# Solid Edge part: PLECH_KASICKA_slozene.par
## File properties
Author: Acer
Template: Iso Metric Part.par
Last saved by: Acer
Revision: 41
Application: Solid Edge
Density: 8027,000 kg/m^3
Accuracy: 0,990
Material Thickness: 2,00 mm
Bend Radius: 1,00 mm
Relief Width: 1,00 mm
Relief Length: 0,00 mm
Neutral Factor: 0,330
Minimum Arc Length: 0,10 mm
Deviational Tolerance: 0,10 mm
Username: Acer
Typ obsahu dokumentu: 0
Material: Stainless Steel, 303
Face Style: Steel
Fill Style: ANSI32(Steel)
Virtual Style: ANSI32(Steel)
Grouping: Metals\Steel
LibraryName: Materials
Coef. of Thermal Exp: 1.7e-05
Thermal Conductivity: 17.0
Specific Heat: 502.0
Modulus of Elasticity: 193053196000.0
Poisson's Ratio: 0.29
Yield Stress: 255106009.0
Ultimate Stress: 579159588.0
Elongation: 0.0
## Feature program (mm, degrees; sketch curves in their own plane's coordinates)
sketch for "unnamed Protrusion 1" plane through (0, 0, 0) normal (0, 0, 1) x-axis (1, 0, 0)
  line (-50, -30) -> (50, -30)
  line (50, -30) -> (50, 30)
  line (50, 30) -> (-50, 30)
  line (-50, 30) -> (-50, -30)
  dimension (linear) = 50
  dimension (linear) = 50
extrude "unnamed Protrusion 1" add finite 60 along +normal
lofted protrusion "unnamed LoftedProtrusion 1"
sketch for "unnamed Cutout 1" plane through (0, 15.408, 79.456) normal (0, 0.8, 0.6) x-axis (-1, 0, 0)
extrude "unnamed Cutout 1" cut through along -normal
Other named dimensions: "Convert_To_Sheet_Metal_4": GapDistance = 0.02 mm
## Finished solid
Body 1: solid body, 80 faces, 170 edges, 92 vertices.
  Faces by surface: plane 56, cylinder 16, spline 8
  Edges by curve: line 122, curve on surface 32, circle 16
Body 2: solid body, 9 faces, 16 edges, 9 vertices.
  Faces by surface: plane 9
  Edges by curve: line 16
Bounding box of the edges (mm; curved faces can reach further): 100.000 x 60.000 x 100.000, from (-50, -30, 0) to (50, 30, 100).
Cylindrical faces by radius (mm): R2 x8, R4 x8
Planar faces by outward normal: +x 8, +y 7, +z 1, -x 8, -y 7, -z 10, oblique 24
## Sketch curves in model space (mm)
line (-50, 27.98, 13.2) -> (-50, 27.98, 4)
line (-50, -27.9912, 13.2) -> (-50, 27.98, 13.2)
line (-50, -27.9912, 4) -> (-50, -27.9912, 13.2)
line (-50, 27.98, 4) -> (-50, -27.9912, 4)
line (50, -27.98, 13.2) -> (50, -27.98, 4)
line (50, 27.9395, 13.2) -> (50, -27.98, 13.2)
line (50, 27.9395, 4) -> (50, 27.9395, 13.2)
line (50, -27.98, 4) -> (50, 27.9395, 4)
line (39.638, 30, 51.6667) -> (39.638, 30, 19.8082)
line (8, 30, 51.6667) -> (39.638, 30, 51.6667)
line (8, 30, 19.8082) -> (8, 30, 51.6667)
line (39.638, 30, 19.8082) -> (8, 30, 19.8082)
line (-35.8415, 30, 13.2) -> (-35.8415, 30, 4)
line (-47.98, 30, 13.2) -> (-35.8415, 30, 13.2)
line (-47.98, 30, 4) -> (-47.98, 30, 13.2)
line (-35.8415, 30, 4) -> (-47.98, 30, 4)
line (47.98, 30, 13.2027) -> (47.98, 30, 4)
line (-14.3234, 30, 13.2027) -> (47.98, 30, 13.2027)
line (-14.3234, 30, 4) -> (-14.3234, 30, 13.2027)
line (47.98, 30, 4) -> (-14.3234, 30, 4)
line (-14.6431, 30, 55.2861) -> (-14.6431, 30, 4)
line (-35.98, 30, 55.2861) -> (-14.6431, 30, 55.2861)
line (-35.98, 30, 4) -> (-35.98, 30, 55.2861)
line (-14.6431, 30, 4) -> (-35.98, 30, 4)
line (8, -30, 51.6667) -> (8, -30, 19.8062)
line (39.64, -30, 51.6667) -> (8, -30, 51.6667)
line (39.64, -30, 19.8062) -> (39.64, -30, 51.6667)
line (8, -30, 19.8062) -> (39.64, -30, 19.8062)
line (-47.98, -30, 13.2) -> (-47.98, -30, 4)
line (47.923, -30, 13.2) -> (-47.98, -30, 13.2)
line (47.923, -30, 4) -> (47.923, -30, 13.2)
line (-47.98, -30, 4) -> (47.923, -30, 4)
line (-39.64, -30, 51.6667) -> (-39.64, -30, 19.8062)
line (-8, -30, 51.6667) -> (-39.64, -30, 51.6667)
line (-8, -30, 19.8062) -> (-8, -30, 51.6667)
line (-39.64, -30, 19.8062) -> (-8, -30, 19.8062)
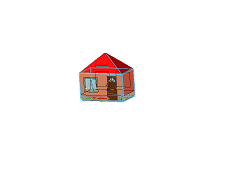
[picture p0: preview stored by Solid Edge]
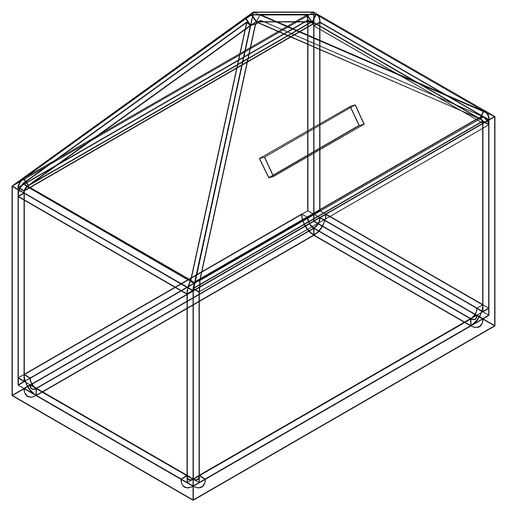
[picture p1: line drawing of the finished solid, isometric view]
